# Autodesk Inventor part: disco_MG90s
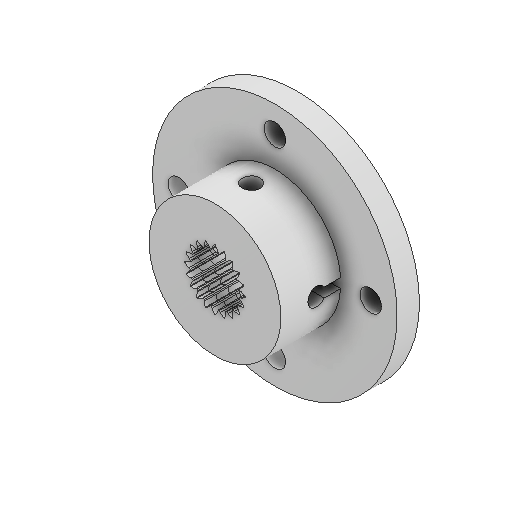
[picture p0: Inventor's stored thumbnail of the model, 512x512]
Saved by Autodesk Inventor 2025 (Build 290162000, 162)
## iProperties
Created: 2020-06
Part Number: disco_MG90s
Material: Generico
Description: FreeCAD Model
Document SubType Name: Modeling
Designer: Ryzen5700u
Density: 1 g/cm^3
Appearance: Default
Author: Ryzen5700u
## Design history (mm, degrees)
feature "Solido1"
node "Solido2"
